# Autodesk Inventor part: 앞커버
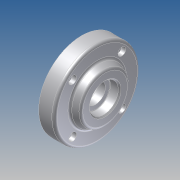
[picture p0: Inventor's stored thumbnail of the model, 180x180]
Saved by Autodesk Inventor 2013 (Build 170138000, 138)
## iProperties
Company: 한국ATC센터
Created: 2009-02
Part Number: 앞커버
Document SubType Name: Modeling
Designer: KYOUNG IL JANG
Density: 2.71 g/cm^3
Mass: 114.339 g
Surface Area: 117.889 cm^2
Volume: 42.1916 cm^3
Material: 알루미늄-6061
Vendor: CBT Solutions
Author: KYOUNG IL JANG
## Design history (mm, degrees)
sketch "스케치1"
  geometry: L1 (-11.5, 0)-(11.5, 0); L2 (11.5, 0)-(11.5, 22.5); L3 (11.5, 22.5)-(6.5, 22.5); L4 (6.5, 22.5)-(6.5, 32.5); L5 (6.5, 32.5)-(-5.5, 32.5); L6 (-5.5, 32.5)-(-5.5, 21); L7 (-5.5, 21)-(-11.5, 18.202); L8 (-11.5, 18.202)-(-11.5, 0); 2 further points
  constraints: 16 end point, 3 parallel, 3 perpendicular, 1 coincident, 1 horizontal, 1 midpoint
  dimensions: "d0" = 23 distance of L1.start L1.end; "d1" = 65 diameter of L5 L1; "d2" = 45 diameter of L3 L1; "d3" = 42 diameter of L6.end L1; "d4" = 115 deg angle of L7 L6; "d5" = 12 distance of L4.end L5.end; "d6" = 5 distance of L2.end L3.end
revolve "회전1" sketch "스케치1" stored, may be unused: angle "d7" = 90 deg
sketch "스케치2"
  geometry: L1 (0, 0)-(32.5, 0); L2 (0, 0)-(18.738, 18.738); 1 further point
  constraints: 4 end point, 1 horizontal, 1 horizontal alignment, 1 other
  dimensions: "d8" = 45 deg angle of L1 L2; "d9" = 26.5 distance of L1.start L2.end
hole "구멍1" sketch "스케치2" at (18.738, 18.738) diameter "d10" = 3.4; stored, may be unused: countersink angle "d14" = 90 deg, drill point angle "d16" = 118 deg; dims "d11" = 6, "d12" = 6, "d13" = 3.3, "d15" = 8
fillet "모깎기1" dims "d20" = 2
hole "구멍2" diameter "d23" = 15; stored, may be unused: countersink angle "d27" = 90 deg, drill point angle "d29" = 118 deg; dims "d21" = 10, "d22" = 10, "d24" = 6, "d25" = 32, "d26" = 10, "d28" = 8
hole "구멍3" diameter "d32" = 22; stored, may be unused: countersink angle "d36" = 90 deg, drill point angle "d38" = 0 deg; dims "d30" = 10, "d31" = 10, "d33" = 6, "d34" = 32, "d35" = 10, "d37" = 7.3
chamfer "모따기1" distance "d39" = 1; stored, may be unused: second distance "d40" = 2, angle "d41" = 45 deg
fillet "모깎기2" dims "d42" = 0.3
node "솔리드1"
pattern_circular "원형 패턴1" dims angle "d18" = 360 deg
